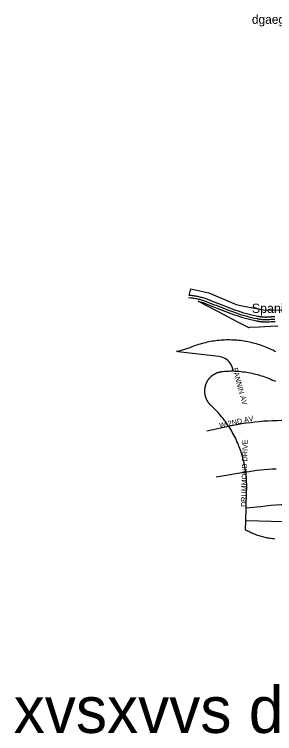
# Model space of a CAD drawing. Extents: x 482780 to 486928, y 5455974 to 5459836.
# Drawn here: x 482780 to 484178, y 5455974 to 5459836 of the extents above; entities that cross this region are included whole.
import ezdxf

# ---------------------------------------------------------------- set-up
doc = ezdxf.new("R2010")
doc.units = 0
for name, color, linetype in [('Default', 7, 'Continuous'), ('ParkLabels', 7, 'Continuous'), ('Parks', 7, 'Continuous'), ('StreetNames', 7, 'Continuous'), ('Streets', 7, 'Continuous')]:
    doc.layers.add(name, color=color, linetype=linetype)

msp = doc.modelspace()

# ---------------------------------------------------------------- linework, layer by layer
at = {"layer": 'Parks'}
for points in [[(484178, 5458211.2), (484177, 5458211.2), (484176, 5458211.3), (484174.9, 5458211.3), (484173.9, 5458211.3), (484172.9, 5458211.3), (484171.9, 5458211.3), (484170.9, 5458211.4), (484169.9, 5458211.3), (484168.9, 5458211.3), (484167.9, 5458211.3), (484166.9, 5458211.3), (484165.8, 5458211.3), (484164.8, 5458211.2), (484163.8, 5458211.2), (484162.8, 5458211.2), (484161.8, 5458211.1), (484160.8, 5458211), (484159.8, 5458211), (484158.8, 5458210.9), (484157.8, 5458210.8), (484156.8, 5458210.7), (484156.8, 5458210.7), (484148.8, 5458210), (484148.8, 5458210), (484147.8, 5458210), (484146.7, 5458209.9), (484145.7, 5458209.8), (484144.7, 5458209.7), (484143.7, 5458209.7), (484142.7, 5458209.6), (484141.7, 5458209.5), (484140.7, 5458209.5), (484139.6, 5458209.4), (484138.6, 5458209.4), (484137.6, 5458209.3), (484136.6, 5458209.3), (484135.6, 5458209.3), (484134.6, 5458209.3), (484133.6, 5458209.2), (484132.5, 5458209.2), (484131.5, 5458209.2), (484130.5, 5458209.2), (484129.5, 5458209.2), (484128.5, 5458209.2), (484127.5, 5458209.2), (484126.4, 5458209.3), (484125.4, 5458209.3), (484124.4, 5458209.3), (484123.4, 5458209.3), (484122.4, 5458209.4), (484121.4, 5458209.4), (484120.4, 5458209.5), (484119.3, 5458209.5), (484118.3, 5458209.6), (484117.3, 5458209.6), (484116.3, 5458209.7), (484115.3, 5458209.8), (484114.3, 5458209.9), (484113.3, 5458209.9), (484112.2, 5458210), (484111.2, 5458210.1), (484110.2, 5458210.2), (484109.2, 5458210.3), (484108.2, 5458210.4), (484107.2, 5458210.6), (484106.2, 5458210.7), (484105.2, 5458210.8), (484104.2, 5458210.9), (484103.2, 5458211.1), (484102.2, 5458211.2), (484101.1, 5458211.3), (484100.1, 5458211.5), (484099.1, 5458211.6), (484098.1, 5458211.8), (484097.1, 5458212), (484096.1, 5458212.1), (484095.1, 5458212.3), (484094.1, 5458212.5), (484093.1, 5458212.7), (484092.1, 5458212.9), (484091.1, 5458213.1), (484090.1, 5458213.3), (484089.1, 5458213.5), (484088.2, 5458213.7), (484087.2, 5458213.9), (484086.2, 5458214.1), (484070.8, 5458217.5), (484056.1, 5458220.8), (484041.6, 5458224.5), (484027.1, 5458228.3), (484012.6, 5458232.5), (483998.2, 5458236.9), (483984, 5458241.5), (483969.7, 5458246.4), (483955.8, 5458251.4), (483955.6, 5458251.5), (483934, 5458259.5), (483877.7, 5458281.1), (483867.6, 5458285), (483867.1, 5458285.2), (483818.9, 5458304.4), (483814.7, 5458306), (483809.3, 5458308), (483803.9, 5458309.9), (483798.4, 5458311.7), (483792.9, 5458313.4), (483787.4, 5458315), (483781.9, 5458316.5), (483776.3, 5458318), (483770.7, 5458319.3), (483765.1, 5458320.5), (483759.4, 5458321.7), (483753.8, 5458322.7), (483748.1, 5458323.6), (483742.4, 5458324.5), (483736.7, 5458325.2), (483731, 5458325.8), (483719.1, 5458327), (483727, 5458361.7), (483824.2, 5458340.2), (483971, 5458278.4), (484012.3, 5458269.9), (484129.2, 5458247.4), (484229.4, 5458250.3)], [(484194.6, 5458161.7), (484153.4, 5458159.6), (484096.5, 5458156.6), (484042.1, 5458153.8), (484037.4, 5458153.5), (484033.2, 5458155.8), (483983.3, 5458181.9), (483930.3, 5458209.6), (483872.5, 5458239.8), (483806.9, 5458274.1), (483766.1, 5458295.5), (483771.1, 5458294.3), (483776.3, 5458292.9), (483781.4, 5458291.5), (483786.5, 5458289.9), (483791.6, 5458288.3), (483796.6, 5458286.6), (483801.6, 5458284.8), (483806.6, 5458283), (483809.4, 5458281.9), (483858.1, 5458262.6), (483868, 5458258.7), (483925.2, 5458236.8), (483947.1, 5458228.6), (483961.6, 5458223.4), (483976.3, 5458218.4), (483991, 5458213.6), (484005.7, 5458209.1), (484020.6, 5458204.9), (484035.5, 5458200.9), (484050.5, 5458197.2), (484065.6, 5458193.7), (484080.9, 5458190.3), (484081.9, 5458190.1), (484082.9, 5458189.9), (484083.9, 5458189.7), (484084.9, 5458189.5), (484085.9, 5458189.3), (484086.9, 5458189.1), (484087.9, 5458188.9), (484088.9, 5458188.7), (484089.9, 5458188.5), (484090.9, 5458188.3), (484091.9, 5458188.2), (484092.9, 5458188), (484093.9, 5458187.8), (484095, 5458187.7), (484096, 5458187.5), (484097, 5458187.4), (484098, 5458187.2), (484099, 5458187.1), (484100, 5458186.9), (484101, 5458186.8), (484102, 5458186.7), (484103, 5458186.6), (484104.1, 5458186.4), (484105.1, 5458186.3), (484106.1, 5458186.2), (484107.1, 5458186.1), (484108.1, 5458186), (484109.1, 5458185.9), (484110.1, 5458185.8), (484111.2, 5458185.7), (484112.2, 5458185.7), (484113.2, 5458185.6), (484114.2, 5458185.5), (484115.2, 5458185.4), (484116.3, 5458185.4), (484117.3, 5458185.3), (484118.3, 5458185.2), (484119.3, 5458185.2), (484120.3, 5458185.1), (484121.3, 5458185.1), (484122.4, 5458185.1), (484123.4, 5458185), (484124.4, 5458185), (484125.4, 5458185), (484126.4, 5458185), (484127.5, 5458184.9), (484128.5, 5458184.9), (484129.5, 5458184.9), (484130.5, 5458184.9), (484131.6, 5458184.9), (484132.6, 5458184.9), (484133.6, 5458184.9), (484134.6, 5458184.9), (484135.6, 5458185), (484136.7, 5458185), (484137.7, 5458185), (484138.7, 5458185.1), (484139.7, 5458185.1), (484140.7, 5458185.1), (484141.8, 5458185.2), (484142.8, 5458185.2), (484143.8, 5458185.3), (484144.8, 5458185.3), (484145.8, 5458185.4), (484146.8, 5458185.5), (484147.9, 5458185.5), (484148.9, 5458185.6), (484149.9, 5458185.7), (484150.9, 5458185.8), (484158.9, 5458186.5), (484161.2, 5458186.7), (484163.6, 5458186.8), (484165.9, 5458186.9), (484168.2, 5458187), (484170.6, 5458187), (484172.9, 5458187), (484175.2, 5458186.9), (484177.5, 5458186.8), (484179.9, 5458186.7)]]:
    msp.add_lwpolyline(points, dxfattribs=at)
at = {"layer": 'Streets'}
for points in [[(483715.9, 5458315.3), (483729.5, 5458313.9), (483735.1, 5458313.2), (483740.7, 5458312.5), (483746.3, 5458311.7), (483751.8, 5458310.7), (483757.4, 5458309.7), (483762.9, 5458308.6), (483768.4, 5458307.4), (483773.9, 5458306.1), (483779.3, 5458304.7), (483784.8, 5458303.1), (483790.2, 5458301.5), (483795.5, 5458299.9), (483800.9, 5458298.1), (483806.2, 5458296.2), (483811.5, 5458294.2), (483814.1, 5458293.2), (483855.3, 5458276.9), (483863, 5458273.9), (483871.8, 5458270.3), (483929.6, 5458248.2), (483951.5, 5458240.1), (483951.6, 5458240), (483965.9, 5458234.8), (483980.3, 5458229.9), (483994.8, 5458225.2), (484009.3, 5458220.8), (484023.9, 5458216.6), (484038.7, 5458212.7), (484053.4, 5458209), (484068.3, 5458205.6), (484083.6, 5458202.2), (484085.6, 5458201.8), (484089.4, 5458201), (484093.1, 5458200.3), (484096.9, 5458199.7), (484100.6, 5458199.2), (484104.4, 5458198.7), (484108.2, 5458198.3), (484111.9, 5458197.9), (484115.7, 5458197.6), (484119.5, 5458197.4), (484123.3, 5458197.2), (484127.1, 5458197.1), (484130.9, 5458197.1), (484134.7, 5458197.1), (484138.5, 5458197.2), (484142.3, 5458197.4), (484146.1, 5458197.6), (484149.9, 5458197.9), (484157.9, 5458198.6), (484160.5, 5458198.8), (484163, 5458199), (484165.6, 5458199.1), (484168.1, 5458199.2), (484170.7, 5458199.2), (484173.3, 5458199.2), (484175.8, 5458199.1), (484178.4, 5458199)], [(484184.9, 5458023.4), (484176.5, 5458027.8), (484168.1, 5458032.1), (484159.5, 5458036.2), (484150.9, 5458040.2), (484142.3, 5458044), (484133.5, 5458047.7), (484124.8, 5458051.2), (484115.9, 5458054.6), (484107, 5458057.8), (484098, 5458060.8), (484089, 5458063.7), (484079.9, 5458066.4), (484070.8, 5458069), (484061.7, 5458071.4), (484052.5, 5458073.7), (484043.3, 5458075.8), (484034, 5458077.7), (484024.7, 5458079.5), (484021.8, 5458080), (484012.5, 5458081.5), (484003.1, 5458082.8), (483993.8, 5458084), (483984.4, 5458085), (483974.9, 5458085.9), (483965.5, 5458086.6), (483956.1, 5458087.1), (483946.6, 5458087.5), (483937.2, 5458087.7), (483927.7, 5458087.7), (483918.2, 5458087.6), (483908.8, 5458087.3), (483899.3, 5458086.8), (483889.9, 5458086.2), (483880.5, 5458085.4), (483871.1, 5458084.4), (483861.7, 5458083.3), (483852.3, 5458082), (483843, 5458080.5), (483833.7, 5458078.9), (483824.4, 5458077.2), (483815.1, 5458075.2), (483805.9, 5458073.1), (483796.7, 5458070.9), (483787.6, 5458068.4), (483778.5, 5458065.9), (483769.4, 5458063.1), (483760.4, 5458060.2), (483751.5, 5458057.2), (483742.6, 5458054), (483733.7, 5458050.6), (483724.9, 5458047.1), (483716.2, 5458043.4), (483657.8, 5458026.2), (483650.1, 5458025.2)], [(483954.7, 5457921.2), (483953.3, 5457929.9), (483951, 5457938.7), (483947.7, 5457947.3), (483943.5, 5457955.5), (483938.5, 5457963.2), (483932.7, 5457970.3), (483926.2, 5457976.8), (483919.1, 5457982.6), (483911.4, 5457987.6), (483903.2, 5457991.7), (483894.7, 5457995), (483885.8, 5457997.4), (483877.7, 5457998.7), (483658.1, 5458024.5), (483650.1, 5458025.2)], [(484021.8, 5457067.2), (484023.1, 5457116.5), (484024.9, 5457184), (484027.3, 5457274.7), (484027.7, 5457290), (484027.8, 5457292.6), (484027.8, 5457303), (484027.7, 5457313.3), (484027.3, 5457323.6), (484026.8, 5457333.9), (484026.2, 5457344.1), (484025.3, 5457354.4), (484024.3, 5457364.7), (484023, 5457374.9), (484022.5, 5457378.9), (484021.6, 5457385.1), (484020.1, 5457395.3), (484018.3, 5457405.5), (484016.4, 5457415.6), (484014.3, 5457425.7), (484012, 5457435.7), (484009.5, 5457445.7), (484006.9, 5457455.7), (484004.1, 5457465.6), (484001.1, 5457475.5), (483997.9, 5457485.3), (483994.6, 5457495.1), (483991.1, 5457504.8), (483987.5, 5457514.4), (483986.1, 5457517.9), (483983.6, 5457524), (483979.6, 5457533.5), (483975.5, 5457542.9), (483971.2, 5457552.3), (483966.7, 5457561.5), (483962, 5457570.7), (483957.2, 5457579.8), (483952.2, 5457588.9), (483947.1, 5457597.8), (483941.8, 5457606.7), (483936.4, 5457615.4), (483930.8, 5457624.1), (483930.2, 5457625), (483925.1, 5457632.7), (483919.2, 5457641.1), (483913.2, 5457649.5), (483907, 5457657.7), (483900.7, 5457665.9), (483894.2, 5457673.9), (483887.6, 5457681.8), (483880.9, 5457689.6), (483874, 5457697.3), (483867, 5457704.9), (483859.9, 5457712.3), (483852.6, 5457719.6), (483845.2, 5457726.8), (483837.7, 5457733.9), (483836.3, 5457735.2), (483835, 5457736.5), (483833.7, 5457737.8), (483832.3, 5457739.2), (483831.1, 5457740.5), (483829.8, 5457741.9), (483828.6, 5457743.4), (483827.4, 5457744.8), (483826.2, 5457746.3), (483825, 5457747.8), (483823.9, 5457749.3), (483822.8, 5457750.8), (483821.7, 5457752.3), (483820.6, 5457753.9), (483819.6, 5457755.5), (483818.6, 5457757.1), (483817.6, 5457758.7), (483816.7, 5457760.3), (483815.8, 5457762), (483814.9, 5457763.6), (483814, 5457765.3), (483813.2, 5457767), (483812.4, 5457768.7), (483811.7, 5457770.4), (483810.9, 5457772.2), (483810.2, 5457773.9), (483809.5, 5457775.7), (483808.9, 5457777.5), (483808.3, 5457779.2), (483807.7, 5457781), (483807.1, 5457782.8), (483806.6, 5457784.6), (483806.1, 5457786.5), (483805.7, 5457788.3), (483805.3, 5457790.1), (483804.9, 5457792), (483804.5, 5457793.8), (483804.2, 5457795.7), (483803.9, 5457797.5), (483803.6, 5457799.4), (483803.4, 5457801.3), (483803.2, 5457803.1), (483803, 5457805), (483802.9, 5457806.9), (483802.8, 5457808.8), (483802.7, 5457810.7), (483802.7, 5457812.6), (483802.7, 5457814.4), (483802.7, 5457816.3), (483802.8, 5457818.2), (483802.9, 5457820.1), (483803, 5457822), (483803.2, 5457823.8), (483803.4, 5457825.7), (483803.6, 5457827.6), (483803.9, 5457829.5), (483804.2, 5457831.3), (483804.5, 5457833.2), (483804.9, 5457835), (483805.3, 5457836.9), (483805.7, 5457838.7), (483806.2, 5457840.5), (483806.6, 5457842.3), (483807.2, 5457844.2), (483807.7, 5457846), (483808.3, 5457847.8), (483808.9, 5457849.5), (483809.6, 5457851.3), (483810.2, 5457853.1), (483810.9, 5457854.8), (483811.7, 5457856.5), (483812.4, 5457858.3), (483813.2, 5457860), (483814.1, 5457861.7), (483814.9, 5457863.3), (483815.8, 5457865), (483816.7, 5457866.7), (483817.7, 5457868.3), (483818.6, 5457869.9), (483819.6, 5457871.5), (483820.7, 5457873.1), (483821.7, 5457874.6), (483822.8, 5457876.2), (483823.9, 5457877.7), (483825, 5457879.2), (483826.2, 5457880.7), (483827.4, 5457882.2), (483828.6, 5457883.6), (483829.8, 5457885), (483831.1, 5457886.4), (483831.3, 5457886.7), (483832.4, 5457887.8), (483833.7, 5457889.2), (483833.9, 5457889.3), (483835.2, 5457890.6), (483836.6, 5457891.8), (483837.9, 5457893.1), (483839.3, 5457894.2), (483840.8, 5457895.4), (483842.2, 5457896.5), (483843.7, 5457897.7), (483845.1, 5457898.7), (483846.6, 5457899.8), (483848.2, 5457900.8), (483849.7, 5457901.8), (483851.2, 5457902.8), (483852.8, 5457903.8), (483854.4, 5457904.7), (483856, 5457905.6), (483857.6, 5457906.5), (483859.2, 5457907.3), (483860.9, 5457908.1), (483862.6, 5457908.9), (483864.2, 5457909.7), (483865.9, 5457910.4), (483867.6, 5457911.1), (483869.3, 5457911.8), (483871, 5457912.4), (483872.8, 5457913), (483874.5, 5457913.6), (483876.3, 5457914.1), (483878, 5457914.6), (483879.8, 5457915.1), (483881.6, 5457915.6), (483883.4, 5457916), (483885.2, 5457916.4), (483887, 5457916.8), (483888.8, 5457917.1), (483890.6, 5457917.4), (483892.4, 5457917.7), (483892.9, 5457917.7), (483900.5, 5457918.6), (483908.1, 5457919.4), (483915.7, 5457920), (483923.3, 5457920.5), (483931, 5457920.9), (483938.6, 5457921.1), (483946.3, 5457921.2), (483953.9, 5457921.2), (483954.7, 5457921.2), (483961.6, 5457921), (483969.2, 5457920.7), (483976.8, 5457920.3), (483984.5, 5457919.7), (483985.6, 5457919.6), (483995.8, 5457918.6), (484006, 5457917.4), (484016.1, 5457916), (484026.2, 5457914.5), (484036.3, 5457912.7), (484046.4, 5457910.8), (484056.4, 5457908.7), (484066.4, 5457906.5), (484076.3, 5457904.1), (484086.2, 5457901.4), (484096, 5457898.7), (484105.8, 5457895.7), (484115.6, 5457892.6), (484125.3, 5457889.3), (484134.9, 5457885.9), (484144.5, 5457882.2), (484154, 5457878.5), (484163.4, 5457874.5), (484172.8, 5457870.4), (484182, 5457866.1)], [(483813.7, 5457599.7), (483930.2, 5457625), (483953.6, 5457629.9), (483977.1, 5457634.4), (484000.6, 5457638.5), (484024.3, 5457642.1), (484048, 5457645.3), (484071.7, 5457648.2), (484095.5, 5457650.6), (484119.3, 5457652.6), (484143.2, 5457654.1), (484167, 5457655.3), (484190.9, 5457656), (484214.8, 5457656.4), (484238.7, 5457656.3), (484262.6, 5457655.8), (484264.4, 5457655.7), (484364.4, 5457653.1), (484476.1, 5457650.3), (484587.9, 5457647.5), (484661.8, 5457645.5), (484809, 5457641.5), (485030, 5457635.6), (485251.1, 5457629.5)], [(483863.3, 5457353.2), (484022.5, 5457378.9), (484040.2, 5457381.8), (484060.9, 5457384.9), (484081.6, 5457387.7), (484102.5, 5457390.1), (484123.3, 5457392.1), (484144.2, 5457393.8), (484165.1, 5457395.1), (484186, 5457396)], [(485239, 5457178.9), (485018, 5457184.6), (484796.9, 5457190.4), (484576, 5457196.2), (484352.4, 5457202.1), (484351.8, 5457202.2), (484323.9, 5457203), (484296, 5457203.4), (484268.1, 5457203.3), (484240.3, 5457202.7), (484212.4, 5457201.6), (484184.6, 5457200), (484156.7, 5457198), (484129, 5457195.4), (484101.2, 5457192.4), (484024.9, 5457184)], [(485015.5, 5457089.7), (484794.5, 5457095.7), (484620.7, 5457100.2), (484573.5, 5457101.4), (484349.9, 5457107.3), (484094.2, 5457114.5), (484023.1, 5457116.5)], [(484179.6, 5457018.7), (484172.9, 5457019.3), (484166.2, 5457020), (484159.6, 5457020.8), (484153, 5457021.8), (484146.3, 5457022.9), (484139.7, 5457024.1), (484133.2, 5457025.4), (484126.6, 5457026.8), (484120.1, 5457028.3), (484113.6, 5457030), (484107.1, 5457031.7), (484100.7, 5457033.6), (484094.3, 5457035.6), (484087.9, 5457037.7), (484081.6, 5457039.9), (484075.3, 5457042.2), (484069.1, 5457044.6), (484062.9, 5457047.1), (484056.7, 5457049.8), (484050.6, 5457052.5), (484044.5, 5457055.4), (484038.5, 5457058.3), (484032.5, 5457061.4), (484026.6, 5457064.6), (484025.2, 5457065.3), (484021.8, 5457067.2)]]:
    msp.add_lwpolyline(points, dxfattribs=at)

# ---------------------------------------------------------------- texts
at = {"layer": 'Default'}
for s, height, p in [('dgaegaer', 48, (484055.5, 5459785.6)), ('xvsxvvs dx', 250, (482775.8, 5455977.3))]:
    msp.add_text(s, height=height, dxfattribs=at).set_placement(p)
at = {"layer": 'ParkLabels'}
msp.add_text('Spanish Banks Beach Park', height=50, dxfattribs=at).set_placement((484055.2, 5458232.7))
at = {"layer": 'StreetNames'}
for s, rotation, p in [('FANNIN AV', 285.0325, (483951.2, 5457934.2)), ('W 2ND AV', 12.1939, (483883.7, 5457614.8)), ('DRUMMOND DRIVE', 88.6402, (484024.8, 5457190.2))]:
    msp.add_text(s, height=28, rotation=rotation, dxfattribs=at).set_placement(p)

doc.saveas('drawing.dxf')
